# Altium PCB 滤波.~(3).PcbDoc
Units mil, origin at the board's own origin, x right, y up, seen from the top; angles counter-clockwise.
Board outline 6000 x 4000 mil, 2 copper layers (Top Layer, Bottom Layer); 19 components, 15 nets, 56 pads, 0 vias.
Unrouted connection lines stored in the file: 40.
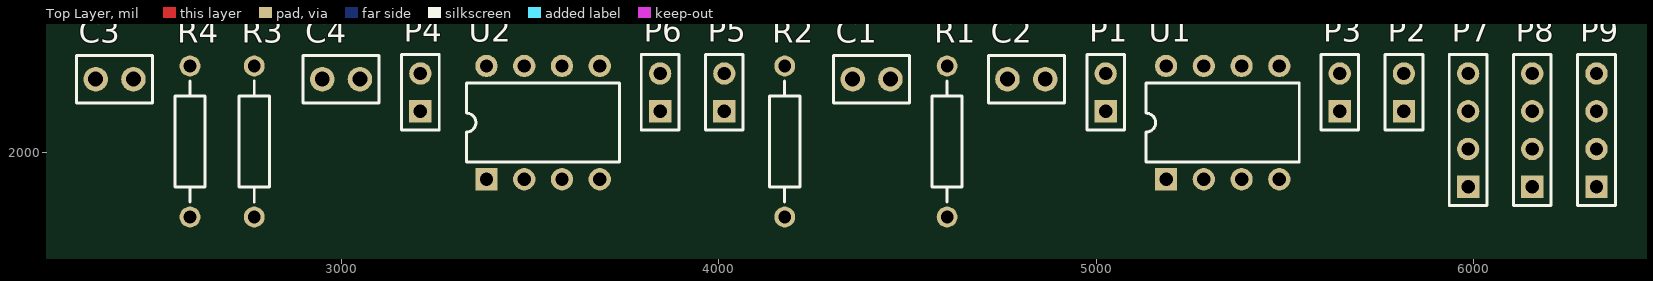
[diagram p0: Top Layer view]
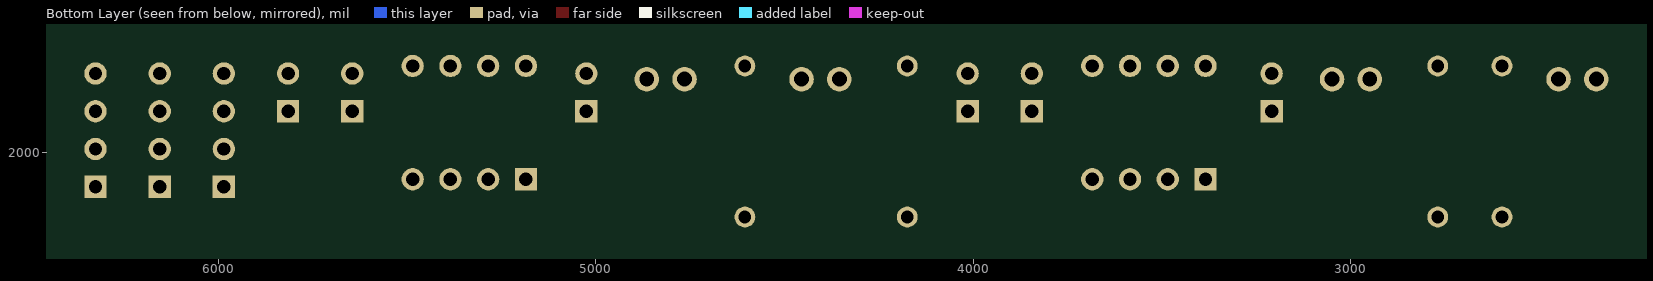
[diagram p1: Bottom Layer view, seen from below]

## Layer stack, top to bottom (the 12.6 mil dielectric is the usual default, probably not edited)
Top Layer: signal copper 1.4
Dielectric: dielectric 12.6, FR-4, Dk 4.8
Bottom Layer: signal copper 1.4

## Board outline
1000,1000 7000,1000 7000,5000 1000,5000

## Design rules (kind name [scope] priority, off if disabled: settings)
Clearance [All] p1: gap=10
PolygonConnect [All] p1: connectstyle=Relief reliefconductorwidth=10 reliefentries=4 polygonreliefangle="90 Angle" airgapwidth=10
RoomDefinition 滤波 [InComponentClass('滤波')] p1: confinementstyle=ConfineIn formatcopy=TRUE lockcomponents=FALSE outline 2290,1790 6400,1790 6400,2370 2290,2370
RoutingVias [All] p1: holewidth=28 width=50 viastyle="Through Hole" minholewidth=28 minwidth=50 maxholewidth=28 maxwidth=50
SolderMaskExpansion [All] p1: expansion=4
Width [All] p1: maxlimit=10 minlimit=10 preferedwidth=10
28 further rules are at their usual default settings.

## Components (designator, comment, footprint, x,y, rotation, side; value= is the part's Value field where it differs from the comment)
C1 "Cap" CAPR2.54-5.1x3.2 4405,2195 r0 top
C2 "Cap" CAPR2.54-5.1x3.2 4815,2195 r0 top
C3 "Cap" CAPR2.54-5.1x3.2 2400,2195 r0 top
C4 "Cap" CAPR2.54-5.1x3.2 3000,2195 r0 top
P1 "Header 2" HDR1X2 5025,2110 r90 top
P2 "Header 2" HDR1X2 5815,2110 r90 top
P3 "Header 2" HDR1X2 5645,2110 r90 top
P4 "Header 2" HDR1X2 3210,2110 r90 top
P5 "Header 2" HDR1X2 4015,2110 r90 top
P6 "Header 2" HDR1X2 3845,2110 r90 top
P7 "Header 4" HDR1X4 5985,1910 r90 top
P8 "Header 4" HDR1X4 6155,1910 r90 top
P9 "Header 4" HDR1X4 6325,1910 r90 top
R1 "Res2" AXIAL-0.4 4605,2030 r90 top
R2 "Res2" AXIAL-0.4 4175,2030 r90 top
R3 "Res2" AXIAL-0.4 2770,2030 r90 top
R4 "Res2" AXIAL-0.4 2600,2030 r90 top
U1 "LM358N" 626-05 5335,2080 r0 top
U2 "LM358N" 626-05 3535,2080 r0 top

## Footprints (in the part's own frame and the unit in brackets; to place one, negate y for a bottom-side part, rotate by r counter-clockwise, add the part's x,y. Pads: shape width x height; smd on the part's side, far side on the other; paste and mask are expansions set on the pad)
626-05 [mm] "DIP; 8 Leads; Row Spacing 7.62 mm; Pitch 2.54 mm"
  rect 1.5x1.5 hole 0.9: 1(-3.81,-3.81)
  round 1.5 hole 0.9: 2(-1.27,-3.81) 3(1.27,-3.81) 4(3.81,-3.81) 5(3.81,3.81) 6(1.27,3.81) 7(-1.27,3.81) 8(-3.81,3.81)
  silkscreen extent -5.15,-2.65 5.15,2.65
AXIAL-0.4 [mm] "Axial Device, Thru-Hole; 2 Leads; 0.4 in Pin Spacing"
  round 1.4 hole 0.85: 1(-5.08,0) 2(5.08,0)
  silkscreen extent -4.06,-1.02 4.06,1.02
CAPR2.54-5.1x3.2 [mm] "Capacitor, Ceramic, Thru-Hole, Dipped Radial; Body 5.1 x 3.2 mm (WxT) Pin Spacing 2.54 mm (typ)"
  round 1.65 hole 1: 1(-1.27,0) 2(1.27,0)
  silkscreen extent -2.55,-1.6 2.55,1.6
HDR1X2 [mm] "Connector; Header; 2 Position"
  rect 1.5x1.5 hole 0.9: 1(0,0)
  round 1.5 hole 0.9: 2(2.54,0)
  silkscreen extent -1.27,-1.27 3.81,1.27
HDR1X4 [mm] "Connector; Header; 4 Position"
  rect 1.5x1.5 hole 0.9: 1(0,0)
  round 1.5 hole 0.9: 2(2.54,0) 3(5.08,0) 4(7.62,0)
  silkscreen extent -1.27,-1.27 8.89,1.27

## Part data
C1 C2 C3 C4: "Capacitor"
P1 P2 P3 P4 P5 P6: "Header, 2-Pin"
P7 P8 P9: "Header, 4-Pin"
R1 R2 R3 R4: "Resistor"
U1 U2: "Dual Low-Power Operational Amplifier"

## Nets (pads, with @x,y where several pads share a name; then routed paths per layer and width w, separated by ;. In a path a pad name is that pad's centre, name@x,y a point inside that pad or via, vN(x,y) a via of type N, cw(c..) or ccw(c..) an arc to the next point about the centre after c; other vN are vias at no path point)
-5: U1.4 U2.4
GND: C1.1 C3.1 R4.1
NetC1_2: C1.2 R1.2 U1.3
NetC2_1: C2.1 P2.1 P2.2 U1.1 U1.2
NetC2_2: C2.2 R2.2 U1.5
NetC3_2: C3.2 R3.2 U2.3
NetC4_1: C4.1 P5.1 P5.2 U2.1 U2.2
NetC4_2: C4.2 R4.2 U2.5
NetP1_1: P1.1 P1.2 R1.1
NetP3_1: P3.1 P3.2 U1.6 U1.7
NetP4_1: P4.1 P4.2 R3.1
NetP6_1: P6.1 P6.2 U2.6 U2.7
NetP8_1: P8.1 P8.2 P8.3 P8.4
NetP9_1: P9.1 P9.2 P9.3 P9.4
VCC: P7.1 P7.2 P7.3 P7.4 U1.8 U2.8
pads on no net: R2.1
